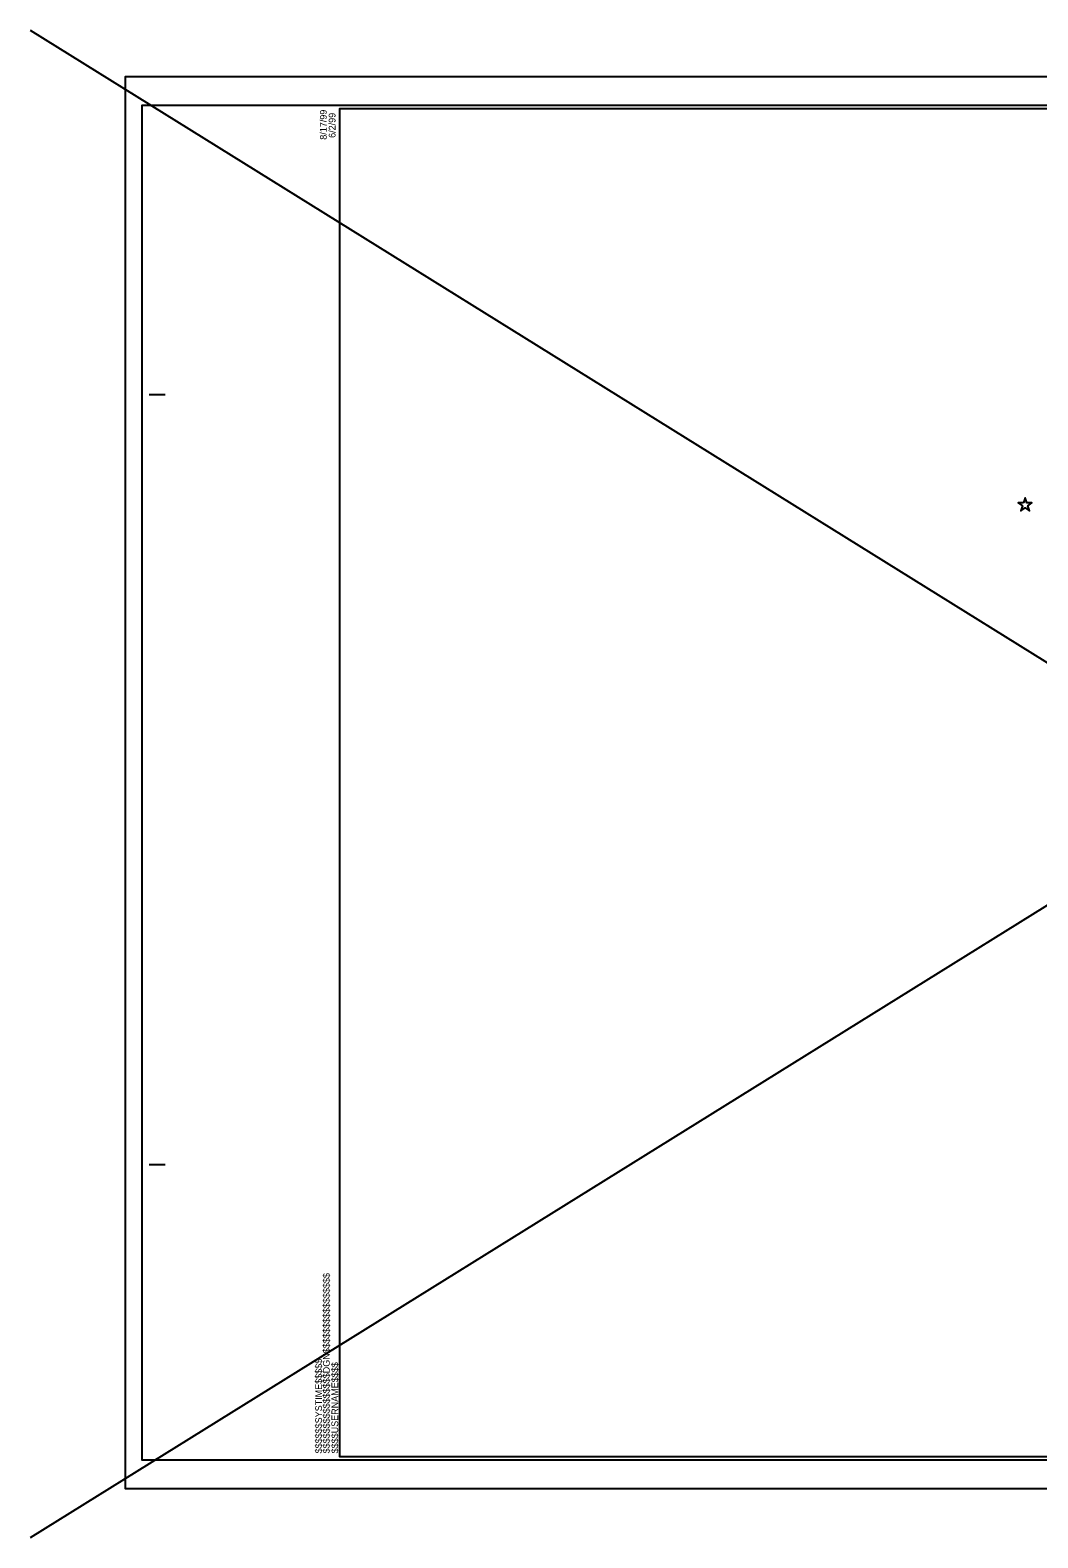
# Model space of a CAD drawing. Extents: x 573813 to 575363, y -54752 to -53123.
# Drawn here: x 573819.6 to 573976.8, y -54752 to -54516.9 of the extents above; entities that cross this region are included whole.
import ezdxf

# ---------------------------------------------------------------- set-up
doc = ezdxf.new("R2010")
doc.units = 0
for name, color, linetype in [('Old_Level_11', 7, 'Continuous'), ('Prop RDY Traffic Signal CELL', 7, 'Continuous'), ('Sheet Plot Border Inside CELL', 7, 'Continuous'), ('Sheet Plot Border Outside CELL', 7, 'Continuous'), ('Sheet Typical CELL', 7, 'Continuous')]:
    doc.layers.add(name, color=color, linetype=linetype)

msp = doc.modelspace()

# ---------------------------------------------------------------- linework, layer by layer
at = {"layer": 'Old_Level_11'}
for p, q in [((574197.59, -54516.9), (573819.63, -54751.97)), ((573819.63, -54516.9), (574197.59, -54751.97))]:
    msp.add_line(p, q, dxfattribs=at)
at = {"layer": 'Prop RDY Traffic Signal CELL'}
msp.add_lwpolyline([(573974.53, -54590.58), (573973.72, -54590.58), (573974.38, -54591.06), (573974.12, -54591.84), (573974.79, -54591.36), (573975.45, -54591.84), (573975.19, -54591.06), (573975.85, -54590.58), (573975.04, -54590.58), (573974.78, -54589.81), (573974.53, -54590.58)], dxfattribs=at)
at = {"layer": 'Sheet Plot Border Inside CELL'}
msp.add_lwpolyline([(574170.55, -54528.66), (573837.07, -54528.66), (573837.07, -54739.79), (574170.55, -54739.79)], close=True, dxfattribs=at)
at = {"layer": 'Sheet Plot Border Outside CELL'}
for p, q in [((574171.45, -54524.16), (573834.47, -54524.16)), ((573834.47, -54524.16), (573834.47, -54744.28)), ((573834.47, -54744.28), (574171.45, -54744.28))]:
    msp.add_line(p, q, dxfattribs=at)
msp.add_lwpolyline([(574171.45, -54524.16), (573834.47, -54524.16), (573834.47, -54744.28), (574171.45, -54744.28)], close=True, dxfattribs=at)
at = {"layer": 'Sheet Typical CELL'}
for p, q in [((573838.17, -54573.69), (573840.67, -54573.69)), ((573838.17, -54573.69), (573840.67, -54573.69)), ((573838.17, -54693.75), (573840.67, -54693.75)), ((573838.17, -54693.75), (573840.67, -54693.75))]:
    msp.add_line(p, q, dxfattribs=at)
msp.add_lwpolyline([(574168.04, -54529.17), (573867.88, -54529.17), (573867.88, -54739.28), (574168.04, -54739.28)], close=True, dxfattribs=at)

# ---------------------------------------------------------------- texts
for s, height, p in [('8/17/99', 1.051, (573865.88, -54533.99)), ('6/2/99', 1.051, (573867.25, -54533.7)), ('$$$$$$$$$$$$$$$$DGN$$$$$$$$$$$$$$$$', 1.0506, (573866.35, -54738.81)), ('$$$$$$$$$$$$$$$$DGN$$$$$$$$$$$$$$$$', 1.0506, (573866.35, -54738.81)), ('$$$$$$SYSTIME$$$$$', 1.0506, (573865.14, -54738.81)), ('$$$$$$SYSTIME$$$$$', 1.0506, (573865.14, -54738.81)), ('$$$$USERNAME$$$$', 1.0506, (573867.67, -54738.8)), ('$$$$USERNAME$$$$', 1.0506, (573867.67, -54738.8))]:
    msp.add_text(s, height=height, rotation=90, dxfattribs=at).set_placement(p)

doc.saveas('drawing.dxf')
